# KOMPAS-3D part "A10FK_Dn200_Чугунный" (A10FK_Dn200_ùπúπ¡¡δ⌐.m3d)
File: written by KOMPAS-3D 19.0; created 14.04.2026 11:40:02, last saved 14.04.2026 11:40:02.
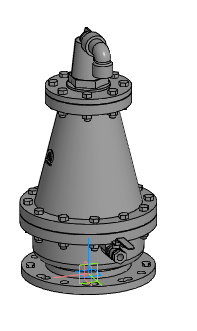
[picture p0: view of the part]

Document properties: Автор: Энергия; Полное имя файла: Z:\3.Личные\kachalov\3d для проектировщиков\x.x Тип A10FK Двухступенчатый воздухоотводчик\stp_Тип A10FK Двухступенчатый воздухоотводчик\A10FK_Dn200_Чугунный.m3d

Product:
- Part/product: A10FK_Dn200_Чугунный

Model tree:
1. Операция без истории:1  (labels: A10FK_Dn200_Чугунный)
